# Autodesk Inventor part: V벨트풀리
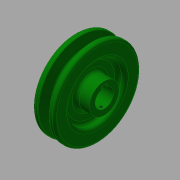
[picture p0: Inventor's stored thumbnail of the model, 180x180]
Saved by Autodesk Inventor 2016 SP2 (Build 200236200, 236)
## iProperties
Created: 2015-11
Part Number: V벨트풀리
Material: 강철, 탄소
Document SubType Name: Modeling
Designer: mduedu
Density: 1 g/cm^3
Appearance: 진녹색
Author: mduedu
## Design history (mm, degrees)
sketch "스케치1"
  geometry: L1 (-9.5, 0)-(9.5, 0); L2 (0, 0)-(0, 37.7); L3 (-4.825, 37.7)-(-9.5, 37.7); L4 (-9.5, 37.7)-(-9.5, 0); L5 (0, 28.7)-(-2.074, 28.7); L6 (-2.074, 28.7)-(-4.825, 37.7); L7 (4.825, 37.7)-(9.5, 37.7); L8 (9.5, 37.7)-(9.5, 0); L9 (0, 28.7)-(2.074, 28.7); L10 (2.074, 28.7)-(4.825, 37.7); L11 (-9.5, 35)-(9.5, 35); 3 further points
  constraints: 22 end point, 7 point on line, 4 perpendicular, 3 symmetric about line, 1 coincident, 1 horizontal, 1 horizontal alignment, 1 midpoint, 1 vertical
  dimensions: "d0" = 19 distance of L1.start L1.end; "d2" = 75.4 diameter of L2.end L1 (derived); "d3" = 34 deg angle of L10 L6; "d4" = 6.3 distance between parallel lines of L11 L9; "d5" = 2.7 distance between parallel lines of L7 L11; "d6" = 8 distance of point (4, 35) point (-4, 35); "d7" = 70 diameter of L11 L1
revolve "회전1" sketch "스케치1" stored, may be unused: angle "d8" = 90 deg
sketch "스케치2"
  geometry: C1 r 24 at (0, 0); C2 r 13 at (0, 0); 1 further point
  constraints: 2 centre point, 2 coincident
  dimensions: "d9" = 48 diameter of C1; "d10" = 26 diameter of C2
extrude "돌출1" cut sketch "스케치2" distance "d11" = 6; taper "d12" = 0 deg
extrude "돌출3" join sketch "스케치2" distance "d37" = 6; taper "d38" = 0 deg
fillet "모깎기1" dims "d13" = 3
fillet "모깎기2" dims "d14" = 3
fillet "모깎기3" dims "d15" = 1, "d16" = 0.5, "d17" = 2
hole "구멍1" diameter "d20" = 16; stored, may be unused: countersink angle "d24" = 90 deg, drill point angle "d26" = 118 deg; dims "d21" = 6, "d22" = 4, "d23" = 2, "d25" = 8, "d53" = 10, "d54" = 10
sketch "스케치3"
  geometry: L1 (-2.5, 0)-(2.5, 0); L2 (2.5, 0)-(2.5, 10.3); L3 (2.5, 10.3)-(-2.5, 10.3); L4 (-2.5, 10.3)-(-2.5, 0); 2 further points
  constraints: 8 end point, 2 parallel, 1 coincident, 1 horizontal, 1 midpoint, 1 perpendicular
  dimensions: "d27" = 5 distance of L2.end L3.end; "d29" = 10.3 distance of L3.end L1.start
extrude "돌출2" cut sketch "스케치3" stored distance "d30" = 6; taper "d31" = 0 deg
node "작업 평면1"
sketch "스케치4"
  geometry: L1 (19, -27)-(19, 27) reference; 2 further points
  constraints: 1 horizontal alignment
  dimensions: "d52" = 22 distance from line of L1 point (-3, 0)
hole "구멍2" sketch "스케치4" at (-3, 0) diameter "d42" = 2.459; stored, may be unused: countersink angle "d46" = 90 deg, drill point angle "d48" = 118 deg; dims "d43" = 6, "d44" = 4, "d45" = 2, "d47" = 8
node "솔리드1"
mirror "대칭1"
